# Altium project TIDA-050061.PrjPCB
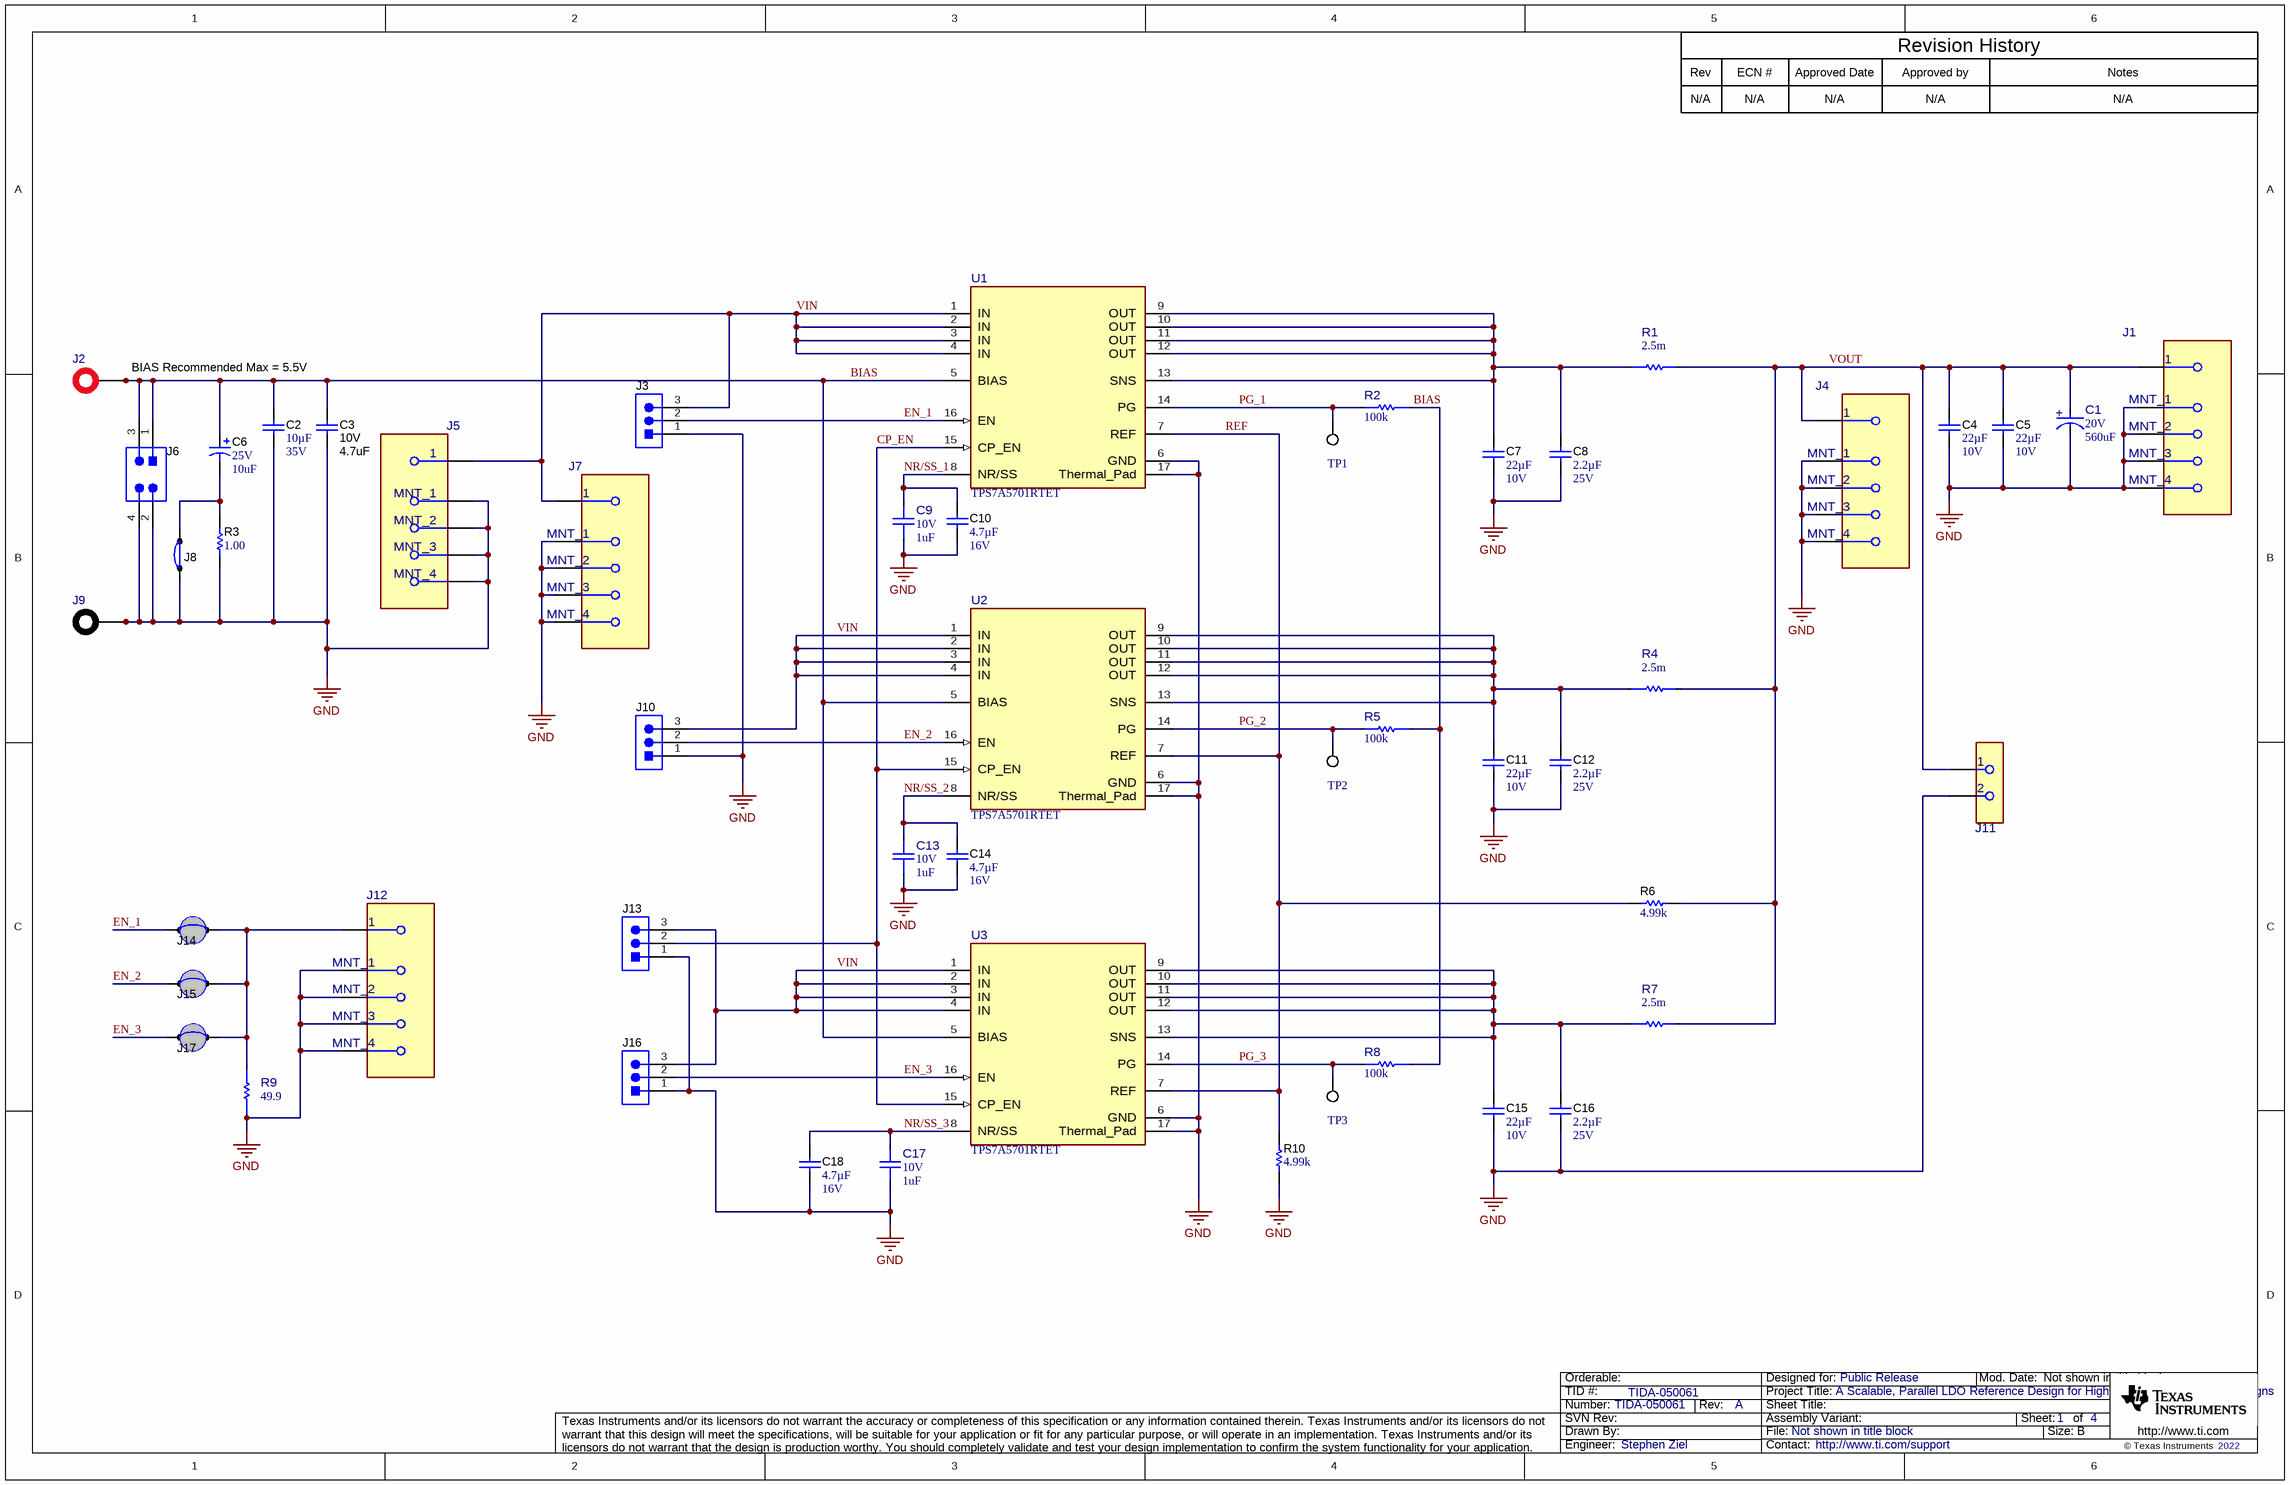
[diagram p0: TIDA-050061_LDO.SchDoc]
TID: TIDA-050061; TechSupport: http://www.ti.com/support; SCH_Rev: A; PRJ_Title: A Scalable, Parallel LDO Reference Design for High Speed and Low Noise Designs; PRJ_Number: TIDA-050061; PRJ_Engineer: Stephen Ziel; PRJ_Customer: Public Release; PCB_Rev: A; PCB_Layout: Stephen Ziel; CopyrightYear: 2022
4 sheets, 179 parts. Net scope: global (net labels, ports and power ports of the same name join across sheets).
Board file: TIDA-050061.PcbDoc
Sheets:
  TIDA-050061_LDO.SchDoc
  TIDA-050061_Load.SchDoc
  TIDA-050061_Input_Cap.SchDoc
  TIDA-050061_Hardware.SchDoc

## Sheet TIDA-050061_LDO.SchDoc
size 431 x 279 mm; Date: Not shown in title block; ApprovedBy: Not shown in title block; CheckedBy: Not shown in title block; Author: Not shown in title block; CompanyName: Not shown in title block; Engineer: Not shown in title block; Organization: Not shown in title block; Address1: Not shown in title block; Address2: Not shown in title block; Address3: Not shown in title block; Address4: Not shown in title block; DocumentNumber: 1; Revision: Use project parameter SCH_Rev; SheetNumber: 1; SheetTotal: 4; PageSetup: Record=PageOptions¦CenterHorizontal=True¦CenterVertical=True¦PrintScale=1.00¦XCorrection=1.00¦YCorrection=1.00¦PrintKind=0¦BorderSize=5000000¦LeftOffset=0¦BottomOffset=0¦Orientation=2¦PaperLength=1000¦PaperWidth=1000¦Scale=100¦PaperSource=15¦PrintQuality=600¦MediaType=1¦DitherType=10¦PaperKind=Letter¦PrintScaleMode=1

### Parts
C1  VDC_V: 20V  ValueDisplayed: 560uF  [FP-20SEF560M_RADIAL-MFG]  (hidden comment: 20SEF560M)
C2  Cap_F: 10µF  VDC_V: 35V  [1210_270]  (hidden comment: GRM32ER7YA106KA12K)
C3  VDC_V: 10V  ValueDisplayed: 4.7uF  [0603]  (hidden comment: C0603C475K8PACTU)
C4  Cap_F: 22µF  VDC_V: 10V  [0805_HV]  (hidden comment: GRM21BZ71A226ME15L)
C5  Cap_F: 22µF  VDC_V: 10V  [0805_HV]  (hidden comment: GRM21BZ71A226ME15L)
C6  VDC_V: 25V  ValueDisplayed: 10uF  [6032-28]  (hidden comment: TPSC106M025R0500)
C7  Cap_F: 22µF  VDC_V: 10V  [0805_HV]  (hidden comment: GRM21BZ71A226ME15L)
C8  Cap_F: 2.2µF  VDC_V: 25V  [0805_HV]  (hidden comment: TMK212B7225KG-TR)
C9  VDC_V: 10V  ValueDisplayed: 1uF  [FP-GMC04X7R105K10NT_0402-IPC_A]  (hidden comment: GMC04X7R105K10NT)
C10  Cap_F: 4.7µF  VDC_V: 16V  [0603]  (hidden comment: GRM188Z71C475KE21D)
C11  Cap_F: 22µF  VDC_V: 10V  [0805_HV]  (hidden comment: GRM21BZ71A226ME15L)
C12  Cap_F: 2.2µF  VDC_V: 25V  [0805_HV]  (hidden comment: TMK212B7225KG-TR)
C13  VDC_V: 10V  ValueDisplayed: 1uF  [FP-GMC04X7R105K10NT_0402-IPC_A]  (hidden comment: GMC04X7R105K10NT)
C14  Cap_F: 4.7µF  VDC_V: 16V  [0603]  (hidden comment: GRM188Z71C475KE21D)
C15  Cap_F: 22µF  VDC_V: 10V  [0805_HV]  (hidden comment: GRM21BZ71A226ME15L)
C16  Cap_F: 2.2µF  VDC_V: 25V  [0805_HV]  (hidden comment: TMK212B7225KG-TR)
C17  VDC_V: 10V  ValueDisplayed: 1uF  [FP-GMC04X7R105K10NT_0402-IPC_A]  (hidden comment: GMC04X7R105K10NT)
C18  Cap_F: 4.7µF  VDC_V: 16V  [0603]  (hidden comment: GRM188Z71C475KE21D)
J1  RF12-07H-T-00-50-G  [FP-RF12-07H-T-00-50-G_CONN_MMCX-MFG]  (value not drawn)
J2  571-0500  [571-0500]  (value not drawn)
J3  61300311121  [WURTH_61300311121]  (value not drawn)
J4  RF2-04A-T-00-50-G  [FP-RF2-04A-T-00-50-G_CONN_RF_7MM00_7MM00-MFG]  (value not drawn)
J5  RF12-07H-T-00-50-G  [FP-RF12-07H-T-00-50-G_CONN_MMCX-MFG]  (value not drawn)
J6  TSW-102-07-G-D  [TSW-102-07-G-D]  (value not drawn)
J7  RF2-04A-T-00-50-G  [FP-RF2-04A-T-00-50-G_CONN_RF_7MM00_7MM00-MFG]  (value not drawn)
J8  JMP-36-30X40SMT  [JMP-36-30X40SMT]  (value not drawn)
J9  571-0100  [571-0100]  (value not drawn)
J10  61300311121  [WURTH_61300311121]  (value not drawn)
J11  691137710002  [FP-691137710002_HDR2-MFG]  (value not drawn)
J12  RF2-04A-T-00-50-G  [FP-RF2-04A-T-00-50-G_CONN_RF_7MM00_7MM00-MFG]  (value not drawn)
J13  61300311121  [WURTH_61300311121]  (value not drawn)
J14  JMP-36-30X40SMT  [JMP-36-30X40SMT]  (value not drawn)
J15  JMP-36-30X40SMT  [JMP-36-30X40SMT]  (value not drawn)
J16  61300311121  [WURTH_61300311121]  (value not drawn)
J17  JMP-36-30X40SMT  [JMP-36-30X40SMT]  (value not drawn)
R1  value 2.5m  [FP-ULR1S-R0025FT2_1206-MFG]  (hidden comment: ULR1S-R0025FT2)
R2  value 100k  [FP-CRCW0402100KFKEDC_0402-IPC_A]  (hidden comment: CRCW0402100KFKEDC)
R3  ValueDisplayed: 1.00  [0805_HV]  (hidden comment: ERJ-6BQF1R0V)
R4  value 2.5m  [FP-ULR1S-R0025FT2_1206-MFG]  (hidden comment: ULR1S-R0025FT2)
R5  value 100k  [FP-CRCW0402100KFKEDC_0402-IPC_A]  (hidden comment: CRCW0402100KFKEDC)
R6  ValueDisplayed: 4.99k  [0402]  (hidden comment: CRCW04024K99FKED)
R7  value 2.5m  [FP-ULR1S-R0025FT2_1206-MFG]  (hidden comment: ULR1S-R0025FT2)
R8  value 100k  [FP-CRCW0402100KFKEDC_0402-IPC_A]  (hidden comment: CRCW0402100KFKEDC)
R9  value 49.9  [FP-CRCW120649R9FKEAHP_1206-MFG]  (hidden comment: CRCW120649R9FKEAHP)
R10  ValueDisplayed: 4.99k  [0402]  (hidden comment: CRCW04024K99FKED)
TP1  5016  [Testpoint_Keystone_Compact]  (value not drawn)
TP2  5016  [Testpoint_Keystone_Compact]  (value not drawn)
TP3  5016  [Testpoint_Keystone_Compact]  (value not drawn)
U1  TPS7A5701RTET  [RTE0016J-OV-MFG]
U2  TPS7A5701RTET  [RTE0016J-OV-MFG]
U3  TPS7A5701RTET  [RTE0016J-OV-MFG]

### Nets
GND: C1.1(CATHODE) C2.2 C3.2 C4.2 C5.2 C7.2 C8.2 C9.1 C10.2 C11.2 C12.2 C13.1 C14.2 C15.2 C16.2 C17.1 C18.2 J1.2(MNT_1) J1.3(MNT_2) J1.4(MNT_3) J1.5(MNT_4) J3.1 J4.2(MNT_1) J4.3(MNT_2) J4.4(MNT_3) J4.5(MNT_4) J5.2(MNT_1) J5.3(MNT_2) J5.4(MNT_3) J5.5(MNT_4) J6.2 J6.4 J7.2(MNT_1) J7.3(MNT_2) J7.4(MNT_3) J7.5(MNT_4) J8.1 J9.1 J9.2 J10.1 J11.2 J12.2(MNT_1) J12.3(MNT_2) J12.4(MNT_3) J12.5(MNT_4) J13.1 J16.1 R3.1 R9.1 R10.1 U1.6(GND) U1.17(Thermal_Pad) U2.6(GND) U2.17(Thermal_Pad) U3.6(GND) U3.17(Thermal_Pad)
BIAS: C2.1 C3.1 C6.1(+) J2.1 J2.2 J6.1 J6.3 R2.1 R5.1 R8.1 U1.5(BIAS) U2.5(BIAS) U3.5(BIAS)
CP_EN: J13.2 U1.15(CP_EN) U2.15(CP_EN) U3.15(CP_EN)
EN_1: J3.2 J14.1 U1.16(EN)
EN_2: J10.2 J15.1 U2.16(EN)
EN_3: J16.2 J17.1 U3.16(EN)
NR/SS_1: C9.2 C10.1 U1.8(NR/SS)
NR/SS_2: C13.2 C14.1 U2.8(NR/SS)
NR/SS_3: C17.2 C18.1 U3.8(NR/SS)
PG_1: R2.2 TP1.1 U1.14(PG)
PG_2: R5.2 TP2.1 U2.14(PG)
PG_3: R8.2 TP3.1 U3.14(PG)
REF: R6.2 R10.2 U1.7(REF) U2.7(REF) U3.7(REF)
VIN: J3.3 J5.1 J7.1 J10.3 J13.3 J16.3 U1.1(IN) U1.2(IN) U1.3(IN) U1.4(IN) U2.1(IN) U2.2(IN) U2.3(IN) U2.4(IN) U3.1(IN) U3.2(IN) U3.3(IN) U3.4(IN)
VOUT: C1.2(ANODE) C4.1 C5.1 J1.1 J4.1 J11.1 R1.2 R4.2 R6.1 R7.2
NetC6_2: C6.2(-) J8.2 R3.2
NetC7_1: C7.1 C8.1 R1.1 U1.9(OUT) U1.10(OUT) U1.11(OUT) U1.12(OUT) U1.13(SNS)
NetC11_1: C11.1 C12.1 R4.1 U2.9(OUT) U2.10(OUT) U2.11(OUT) U2.12(OUT) U2.13(SNS)
NetC15_1: C15.1 C16.1 R7.1 U3.9(OUT) U3.10(OUT) U3.11(OUT) U3.12(OUT) U3.13(SNS)
NetJ12_1: J12.1 J14.2 J15.2 J17.2 R9.2

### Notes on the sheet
- Rev
- N/A
- ECN #
- Approved Date
- Approved by
- Revision History
- Notes
- BIAS Recommended Max = 5.5V

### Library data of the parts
C1 = CMP-0093206-1: Cap Aluminum Polymer 560uF 20VDC 20% (10 X 13mm) Radial 5mm 0.012 Ohm 1700mA 1000h 125C; Manufacturer: Panasonic; Cap_F: 560µF; IRMS_A: 1.7A; AEC Qualified: No; Value: 560µF; Dissipation Factor: 12%; Life: 1000Hours; Leakage Current: 2240uA; Esr: 12m
C2 = CMP-0081639-1: CAP, CERM, 10 µF, 35 V,+/- 10%, X7R, 1210; Manufacturer: MuRata; Value: 10uF; SizeZ_mm: 2.7; AEC Qualified: N; TaMin_C: -55°C; ESR_ohm: 1m; SizeAreaWB_mm2: 14.7; Value1: 0.001 ohm; U/M: EA; TaMax_C: 125°C; SizeX_mm: 3.2; SizeY_mm: 2.5; Cap_Case: 1210; SizeArea_mm2: 8; IRMS_A: 6A; AEC Category: Q200
C3 = CMP-0006949-4: CAP, CERM, 4.7 uF, 10 V, +/- 10%, X5R, 0603; Manufacturer: Kemet; TaMin_C: -55°C; ESR_ohm: 6m; Polarized: N; SizeAreaWB_mm2: 4.68; Value1: 0.006 ohm; U/M: EA; Value: 4.7uF; TaMax_C: 85°C; SizeZ_mm: 1; SizeX_mm: 1.6; SizeY_mm: 0.8; SizeArea_mm2: 1.28; Cap_F: 4.7µF; IRMS_A: 7.24A; AEC Category: Q200
C4 C5 C7 C11 C15 = CMP-0008377-2: CAP, CERM, 22 uF, 10 V, +/- 20%, X7R, 0805; Manufacturer: MuRata; SizeY_mm: 1.25; Cap_Case: 0805; SizeArea_mm2: 2.5; AEC Qualified: N; AEC Category: Q200; ValueDisplayed: 22uF; TaMin_C: -55°C; SizeAreaWB_mm2: 6.75; Value1: Unknown; U/M: EA; Value: 22uF; TaMax_C: 125°C; SizeZ_mm: 1.45; SizeX_mm: 2
C6 = CMP-0011645-1: CAP, TA, 10 uF, 25 V, +/- 20%, 0.5 ohm, SMD; Manufacturer: AVX; TaMin_C: -55°C; ESR_ohm: 0.5; Polarized: Y; SizeAreaWB_mm2: 41.6; Value1: 0.5 ohm; U/M: EA; Value: 10uF; TaMax_C: 125°C; SizeZ_mm: 2.8; SizeX_mm: 6; SizeY_mm: 3.2; Cap_Case: C; SizeArea_mm2: 19.2; CompType: Capacitor; Cap_F: 10µF; IRMS_A: 422mA; AEC Category: Q200
C8 C12 C16 = CMP-0080705-2: CAP, CERM, 2.2 µF, 25 V,+/- 10%, X7R, 0805; Manufacturer: Taiyo Yuden; SizeY_mm: 1.25; Cap_Case: 0805; SizeArea_mm2: 2.5; AEC Qualified: N; AEC Category: Q200; TaMin_C: -55°C; SizeAreaWB_mm2: 6.75; U/M: EA; Value: 2.2uF; TaMax_C: 125°C; SizeZ_mm: 1.45; SizeX_mm: 2
C9 C13 C17 = CMP-0093200-1: 1µF ±10% 10V Ceramic Capacitor X7R 0402 (1005 Metric); Manufacturer: Cal-Chip Electronics; TempCo: 15%; SizeZ_mm: 0.6mm; AEC Qualified: No
C10 C14 C18 = CMP-0064936-1: CAP, CERM, 4.7 uF, 16 V,+/- 10%, X7R, 0603; Manufacturer: MuRata; TaMin_C: -55°C; Polarized: N; SizeAreaWB_mm2: 4.68; Value1: Unknown; U/M: EA; Value: 4.7uF; TaMax_C: 125°C; SizeZ_mm: 1; SizeX_mm: 1.6; SizeY_mm: 0.8; SizeArea_mm2: 1.28; AEC Category: Q200
J1 J5 = CMP-0096285-1: MMCX Connector Jack, Female Socket 50Ohm Through Hole Solder; Manufacturer: Adam Tech; ContactFinish: Gold; Is Female: yes; Dielectric Material: TEFLON; SizeZ_mm: 0.207inch; Impedance: 50Ω; AEC Qualified: No; Conn Orientation: Vertical
J2 = CMP-0055393-3: Standard Banana Jack, insulated, 10A, red; Manufacturer: DEM Manufacturing; Green_REACh: Incomplete; Green_Lifecycle: Not Set
J3 J10 J13 J16 = CMP-0054796-2: Header, 2.54 mm, 3x1, Gold, TH; Manufacturer: Wurth Elektronik; Green_REACh: Passed; Green_Lifecycle: Active; Cert_UL: Y; Gender: Male; Pitch_mm: 2.54; Row_Count: 1; Shrouded: N
J4 J7 = CMP-0096117-1: SMA Connector Jack, Female Socket 50Ohm Through Hole Solder; Manufacturer: Adam Tech; ContactFinish: Gold; Voltage_V: 500V; AEC Qualified: No; Impedance: 50Ω; Dielectric Material: PTFE; Is Female: yes; SizeZ_mm: 0.407inch; Frequency_Fixed: 6GHz; Conn Orientation: Vertical
J6 = CMP-0075404-1: Header, 100mil, 2x2, Gold, TH; Manufacturer: Samtec; Pitch_mm: 2.54; Cert_VDE: N; Gender: Male; Cert_CSA: Y; Voltage_V: 550V; Green_REACh: Passed; Current_A: 6.3A; CT: False; Green_Lifecycle: Active; Row_Count: 2; CNHeader: True
J8 J14 J15 J17 = CMP-0003883-1: Jumper, SMT; Manufacturer: Any
J9 = CMP-0055389-3: Standard Banana Jack, insulated, 10A, black; Manufacturer: DEM Manufacturing; Green_REACh: Incomplete; Green_Lifecycle: Not Set
J11 = CMP-0087503-1: TERM BLK 2POS SIDE ENTRY 5MM PCB; Manufacturer: Würth Elektronik; ContactFinish: Tin,Nickel; Current_A: 16A; Row_Count: 1; Voltage_V: 300V; Symbol Name: SYM-691137710002
J12 = CMP-0096117-1: SMA Connector Jack, Female Socket 50Ohm Through Hole Solder; Manufacturer: Adam Tech; AEC Qualified: No; Impedance: 50Ω; Dielectric Material: PTFE; Is Female: yes; SizeZ_mm: 0.407inch; Frequency_Fixed: 6GHz; Conn Orientation: Vertical; Voltage_V: 500V; ContactFinish: Gold
R1 R4 R7 = CMP-0095593-1: Fixed Resistor, Metal Alloy, 1W, 0.0025ohm, 1% +/-Tol, 50ppm/Cel, Surface Mount, 1206; Manufacturer: Welwyn; TempCo: 50ppm/°C; SizeZ_mm: 0.8mm; AEC Qualified: Yes; AEC Grade: Grade 0
R2 R5 R8 = CMP-0092204-1: 100 kOhms ±1% 0.063W, 1/16W Chip Resistor 0402 (1005 Metric)  Thick Film; Manufacturer: Vishay; Power_W: 63mW; AEC Qualified: No; TempCo: 100ppm/°C; SizeZ_mm: 0.35mm; VDC_V: 50V
R3 = CMP-0074786-1: RES, 1.00, 1%, 0.333 W, AEC-Q200 Grade 1, 0805; Manufacturer: Panasonic; Power_W: 333mW; TempCo: 200 ppm/C; Value_Code: 1R00; U/M: EA; Value: 1.00; EIA_Code: E96; Res_ohm: 1; SizeX_mm: 2.0; SizeY_mm: 1.25; SizeZ_mm: 1.45; Value2: 0.333W; SizeArea_mm2: 2.5; AEC Qualified: Y; AEC Category: Q200
R6 R10 = CMP-0026414-2: RES, 4.99 k, 1%, 0.063 W, AEC-Q200 Grade 0, 0402; Manufacturer: Vishay-Dale; Power_W: 63mW; TempCo: 100 ppm/C; Value_Code: 4k99; Value: 4.99k; EIA_Code: E96; SizeX_mm: 1; SizeY_mm: 0.5; SizeZ_mm: 0.6; Value2: 0.063W; AEC Qualified: Y; VDC_V: 50V; AEC Category: Q200; AEC Grade: 0
R9 = CMP-0093196-1: RES Thick Film, 49.9Ω, 1%, 0.75W, 100ppm/°C, 1206; Manufacturer: Vishay Dale; Power_W: 750mW; SizeZ_mm: 0.65mm; AEC Qualified: Yes; AEC Grade: Grade 0; VDC_V: 200V
TP1-TP3 = CMP-0055153-1: Test Point, Compact, SMT; Manufacturer: Keystone; CNHeader: FALSE; Green_Lifecycle: Active; Green_REACh: Passed; CT: TRUE
U1-U3 = CMP-0090637-2: 5-A, Low-VIN (0.7V), Low-Noise, High-Accuracy, Ultra-Low Dropout (LDO) Voltage Regulator; Manufacturer: Texas Instruments; Max Supply Voltage: 6V; Min Supply Voltage: 700mV; Standoff Height: 0mm; Dropout Voltage: 100mV; Number Of Outputs: 1; AEC Category: Q200; Nominal Supply Current: 10mA; Output Type: AdjustableProgrammable; Accuracy Percentage: 1%; AEC Qualified: Yes; Output Voltage: 0.5-5.2V; CompType: IC; TJmax_C: +125°C; SizeZ_mm: 0.8mm

## Sheet TIDA-050061_Load.SchDoc
size 431 x 279 mm; Date: Not shown in title block; ApprovedBy: Not shown in title block; CheckedBy: Not shown in title block; Author: Not shown in title block; CompanyName: Not shown in title block; Engineer: Not shown in title block; Organization: Not shown in title block; Address1: Not shown in title block; Address2: Not shown in title block; Address3: Not shown in title block; Address4: Not shown in title block; DocumentNumber: 2; Revision: Use project parameter SCH_Rev; SheetNumber: 2; SheetTotal: 4; PageSetup: Record=PageOptions¦CenterHorizontal=True¦CenterVertical=True¦PrintScale=1.00¦XCorrection=1.00¦YCorrection=1.00¦PrintKind=0¦BorderSize=5000000¦LeftOffset=0¦BottomOffset=0¦Orientation=2¦PaperLength=1000¦PaperWidth=1000¦Scale=100¦PaperSource=15¦PrintQuality=600¦MediaType=1¦DitherType=10¦PaperKind=Letter¦PrintScaleMode=1
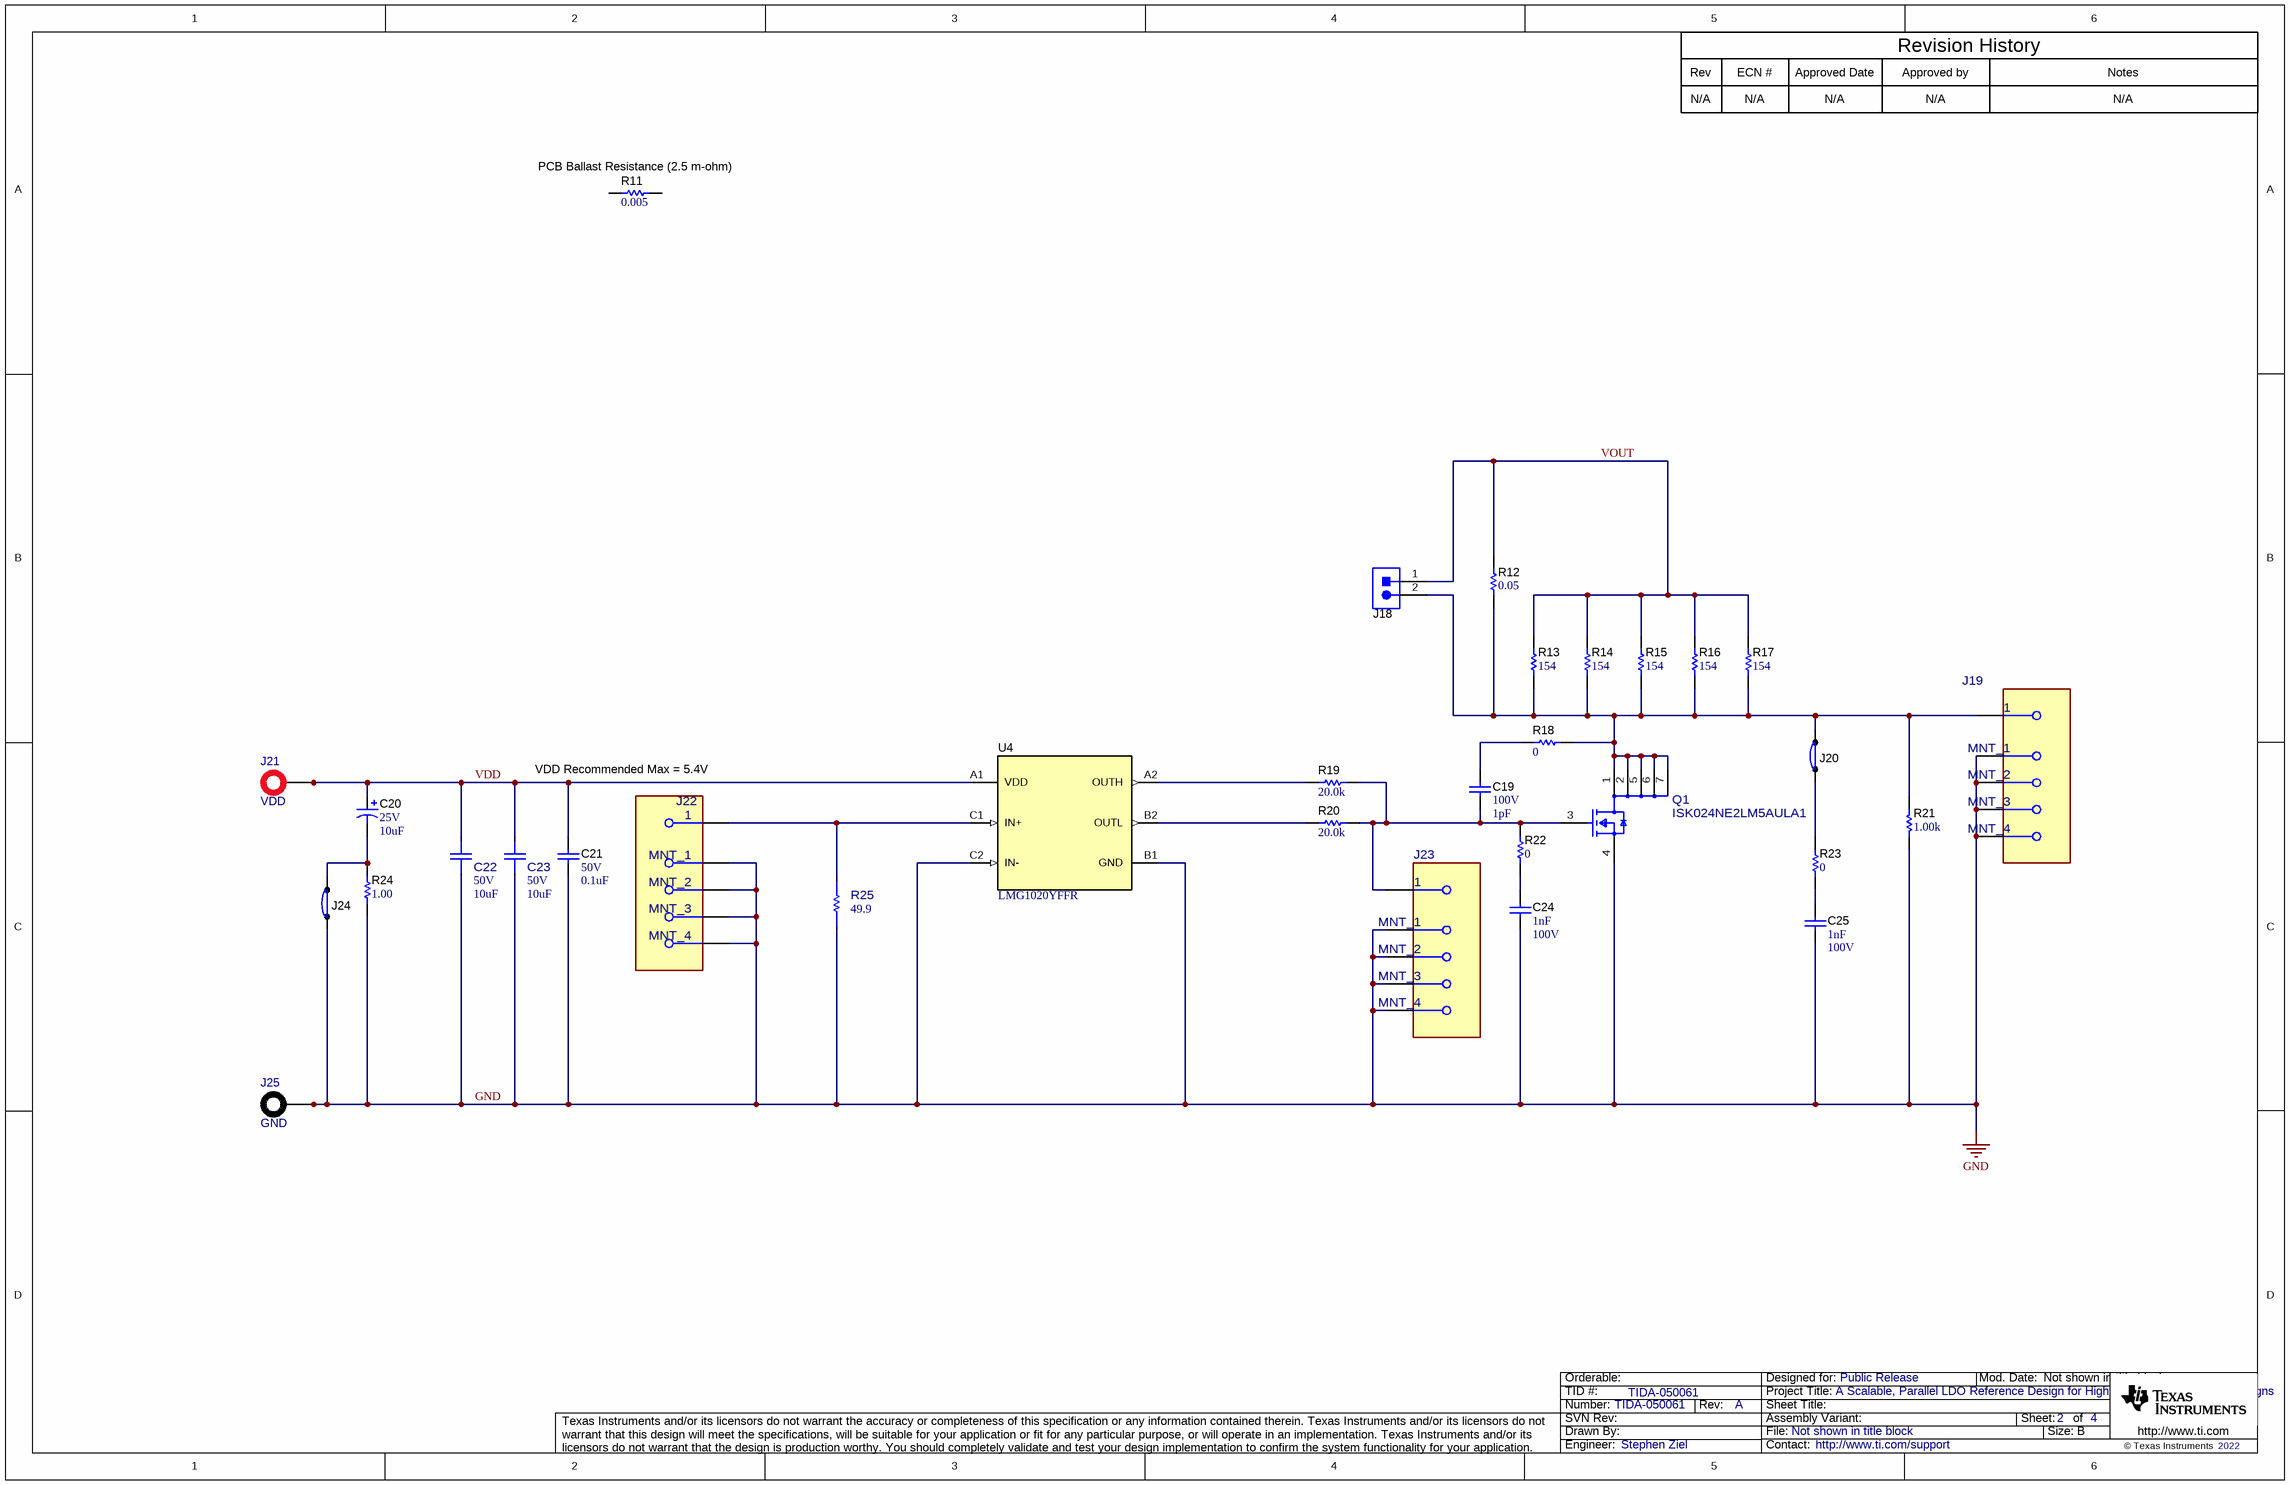
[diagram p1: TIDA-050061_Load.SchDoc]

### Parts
C19  VDC_V: 100V  ValueDisplayed: 1pF  [0805]  (hidden comment: CL05A105KP5NNNC-R)
C20  VDC_V: 25V  ValueDisplayed: 10uF  [6032-28]  (hidden comment: TPSC106M025R0500)
C21  VDC_V: 50V  ValueDisplayed: 0.1uF  [0402]  (hidden comment: C1005X7R1H104K050BB)
C22  VDC_V: 50V  ValueDisplayed: 10uF  [FP-GMC31X7R106K50NT_1206-MFG]  (hidden comment: GMC31X7R106K50NT)
C23  VDC_V: 50V  ValueDisplayed: 10uF  [FP-GMC31X7R106K50NT_1206-MFG]  (hidden comment: GMC31X7R106K50NT)
C24  Cap_F: 1nF  VDC_V: 100V  [0603]  (hidden comment: 06031C102JAT2A)
C25  Cap_F: 1nF  VDC_V: 100V  [0603]  (hidden comment: 06031C102JAT2A)
J18  PBC02SAAN  [Sullins_PBC02SAAN]  (value not drawn)
J19  RF12-07H-T-00-50-G  [FP-RF12-07H-T-00-50-G_CONN_MMCX-MFG]  (value not drawn)
J20  JMP-36-30X40SMT  [JMP-36-30X40SMT]  (value not drawn)
J21  VDD  [571-0500]
J22  RF2-04A-T-00-50-G  [FP-RF2-04A-T-00-50-G_CONN_RF_7MM00_7MM00-MFG]  (value not drawn)
J23  RF12-07H-T-00-50-G  [FP-RF12-07H-T-00-50-G_CONN_MMCX-MFG]  (value not drawn)
J24  JMP-36-30X40SMT  [JMP-36-30X40SMT]  (value not drawn)
J25  GND  [571-0100]
Q1  ISK024NE2LM5AULA1  [FP-ISK024NE2LM5AULA1_VSON6-MFG]
R11  ValueDisplayed: 0.005  [1206]  (hidden comment: WSL12065L000FEA18)
R12  ValueDisplayed: 0.05  [0612]  (hidden comment: ERJ-B2CFR05V)
R13  ValueDisplayed: 154  [1210]  (hidden comment: RC1210FR-07154RL)
R14  ValueDisplayed: 154  [1210]  (hidden comment: RC1210FR-07154RL)
R15  ValueDisplayed: 154  [1210]  (hidden comment: RC1210FR-07154RL)
R16  ValueDisplayed: 154  [1210]  (hidden comment: RC1210FR-07154RL)
R17  ValueDisplayed: 154  [1210]  (hidden comment: RC1210FR-07154RL)
R18  ValueDisplayed: 0  [0805_HV]  (hidden comment: ERJ-6GEY0R00V)
R19  ValueDisplayed: 20.0k  [0603]  (hidden comment: RC0603FR-0720KL)
R20  ValueDisplayed: 20.0k  [0603]  (hidden comment: RC0603FR-0720KL)
R21  ValueDisplayed: 1.00k  [0805_HV]  (hidden comment: ERJ-6ENF1001V)
R22  ValueDisplayed: 0  [0603]  (hidden comment: RMCF0603ZT0R00)
R23  ValueDisplayed: 0  [0603]  (hidden comment: RMCF0603ZT0R00)
R24  ValueDisplayed: 1.00  [0805_HV]  (hidden comment: ERJ-6BQF1R0V)
R25  value 49.9  [FP-CRCW120649R9FKEAHP_1206-MFG]  (hidden comment: CRCW120649R9FKEAHP)
U4  LMG1020YFFR  [YFF0006AEAE]

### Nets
GND: C21.2 C22.1 C23.1 C24.2 C25.2 J19.2(MNT_1) J19.3(MNT_2) J19.4(MNT_3) J19.5(MNT_4) J22.2(MNT_1) J22.3(MNT_2) J22.4(MNT_3) J22.5(MNT_4) J23.2(MNT_1) J23.3(MNT_2) J23.4(MNT_3) J23.5(MNT_4) J24.1 J25.1 J25.2 Q1.4(SOURCE) R21.1 R24.1 R25.1 U4.B1(GND) U4.C2(IN-)
VDD: C20.1(+) C21.1 C22.2 C23.2 J21.1 J21.2 U4.A1(VDD)
VOUT: J18.1 R12.2 R13.2 R14.2 R15.2 R16.2 R17.2
NetC19_1: C19.1 R18.1
NetC19_2: C19.2 J23.1 Q1.3(GATE) R19.2 R20.2 R22.2
NetC20_2: C20.2(-) J24.2 R24.2
NetC24_1: C24.1 R22.1
NetC25_1: C25.1 R23.1
NetJ18_2: J18.2 J19.1 J20.2 Q1.1(DRAIN) Q1.2(DRAIN) Q1.5(DRAIN) Q1.6(DRAIN) Q1.7(DRAIN) R12.1 R13.1 R14.1 R15.1 R16.1 R17.1 R18.2 R21.2
NetJ20_1: J20.1 R23.2
NetJ22_1: J22.1 R25.2 U4.C1(IN+)
NetR19_1: R19.1 U4.A2(OUTH)
NetR20_1: R20.1 U4.B2(OUTL)

Not connected (* = marked no-connect by the designer): R11 1 2

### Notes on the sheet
- Rev
- N/A
- ECN #
- Approved Date
- Approved by
- Revision History
- Notes
- (near R11) PCB Ballast Resistance (2.5 m-ohm)
- VDD Recommended Max = 5.4V

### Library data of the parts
C19 = CMP-0008040-1: CAP, CERM, 1 pF, 100 V, +/- 5%, C0G/NP0, 0805; Manufacturer: MuRata; PartNumber: GQM2195C2A1R0CB01D; TaMin_C: -55°C; Polarized: N; SizeAreaWB_mm2: 6.75; Value1: Unknown; U/M: EA; Value: 1pF; TaMax_C: 125°C; SizeZ_mm: 1.45; SizeX_mm: 2; SizeY_mm: 1.25; SizeArea_mm2: 2.5; AEC Category: Q200
C20 = CMP-0011645-1: as C6 on sheet TIDA-050061_LDO
C21 = CMP-0006297-2: CAP, CERM, 0.1 uF, 50 V, +/- 10%, X7R, 0402; Manufacturer: TDK; TaMin_C: -55°C; ESR_ohm: 39.064m; Polarized: N; SizeAreaWB_mm2: 3; Value1: 0.039064 ohm; U/M: EA; Value: 0.1uF; TaMax_C: 125°C; SizeZ_mm: 0.6; SizeX_mm: 1; SizeY_mm: 0.5; Cap_F: 100nF; IRMS_A: 814.669mA; AEC Category: Q200
C22 C23 = CMP-0093201-1: 10 µF ±10% 50V Ceramic Capacitor X7R 1206 (3216 Metric); Manufacturer: Cal-Chip Electronics; TempCo: 15%; Value: 10µF; SizeZ_mm: 1.8mm; AEC Qualified: No
C24 C25 = CMP-0006723-4: CAP, CERM, 1000 pF, 100 V, +/- 5%, X7R, 0603; Manufacturer: AVX; Value: 1000pF; SizeZ_mm: 1; AEC Qualified: N; TaMin_C: -55°C; ESR_ohm: 0.276; SizeAreaWB_mm2: 4.68; Value1: 0.276 ohm; U/M: EA; TaMax_C: 125°C; SizeX_mm: 1.6; SizeY_mm: 0.8; SizeArea_mm2: 1.28; AEC Category: Q200
J18 = CMP-0054566-1: Header, 100mil, 2x1, Gold, TH; Manufacturer: Sullins Connector Solutions; CNHeader: TRUE; Current_A: 3A; Green_Lifecycle: Active; Shrouded: N; Gender: Male; Green_REACh: Passed; Voltage_V: 1.8kV; Row_Count: 1; Pitch_mm: 2.54; CT: FALSE; Cert_UL: Y
J19 J23 = CMP-0096285-1: as J1 on sheet TIDA-050061_LDO
J20 J24 = CMP-0003883-1: Jumper, SMT; Manufacturer: Any
J21 = CMP-0055393-3: as J2 on sheet TIDA-050061_LDO
J22 = CMP-0096117-1: as J4 on sheet TIDA-050061_LDO
J25 = CMP-0055389-3: as J9 on sheet TIDA-050061_LDO
Q1 = CMP-0095537-1: 40 V optiMOS Power Transistor, Surface Mount 6-PQFN Dual (2x2); Manufacturer: Infineon; QgTyp_nC: 14.8nC @ 10V; Vgs_V: 16V; Threshold Vgs Min: 1.2V; Reverse Recovery Charge: 15.2nC; AEC Qualified: No; Pulse Drain Current: 221A; IdsMax_A: 20A; Rdson45_ohm: 1.9m; Number Of N Channels: 1; VdsMax_V: 1V; Transconductance: 100S; Turn On Delay Time: 7.2ns; Input Capacitace At Vds: 960pF @ 12V; ChMode: False; Power_W: 2.1W; Reverse Recovery Time: 23.6ns; Typ Forward Diode Voltage: 0.81V; SizeZ_mm: 0.9mm; Turn Off Delay Time: 14.6ns; TJmax_C: +150°C; Drain To Source Breakdown Voltage: 25V; Threshold Vgs Max: 2V
R11 = CMP-0084633-1: RES, 0.005, 1%, 0.5 W, AEC-Q200 Grade 0, 1206; Manufacturer: Vishay-Dale; Value_Code: 5L000; SizeArea_mm2: 5.12; Value: 0.005; SizeY_mm: 1.6; TempCo: 110 ppm/C; Value2: 0.5W; SizeZ_mm: 1.35; Res_ohm: 5m; Green_REACh: Incomplete; Power_W: 500mW; SizeX_mm: 3.2; AEC Qualified: Y; SizeAreaWB_mm2: 10.92; Green_Lifecycle: Active; EIA_Code: E96; AEC Grade: 0; AEC Category: Q200
R12 = CMP-0015056-3: RES, 0.05, 1%, 1 W, AEC-Q200 Grade 0, 0612; Manufacturer: Panasonic; Value_Code: R050; SizeZ_mm: 0.85; TempCo: 150 ppm/C; SizeAreaWB_mm2: 10.92; AEC Grade: 0; SizeY_mm: 3.2; AEC Qualified: Y; U/M: EA; AEC Category: Q200; EIA_Code: E96; SizeX_mm: 1.6; Value2: 1W; Value: 0.05; Res_ohm: 50m; SizeArea_mm2: 5.12
R13-R17 = CMP-0082786-1: RES, 154, 1%, 0.5 W, 1210; Manufacturer: Yageo; Power_W: 500mW; TempCo: 100 ppm/C; SizeAreaWB_mm2: 14.7; Value_Code: 154R; Value: 154; EIA_Code: E96; SizeX_mm: 3.2; SizeY_mm: 2.5; SizeZ_mm: 1.35; Value2: 0.5W; SizeArea_mm2: 8; AEC Qualified: N; VDC_V: 200V; AEC Category: Q200
R18 = CMP-0020616-3: RES, 0, 5%, 0.125 W, AEC-Q200 Grade 0, 0805; Manufacturer: Panasonic; Power_W: 125mW; TempCo: 600 ppm/C; Value_Code: 0000; Value: 0; EIA_Code: E24; SizeX_mm: 2; SizeY_mm: 1.25; SizeZ_mm: 1.45; Value2: 0.125W; SizeArea_mm2: 2.5; AEC Qualified: Y; VDC_V: 150V; AEC Category: Q200; SizeAreaWB_mm2: 6.75
R19 R20 = CMP-0022906-5: RES, 20.0 k, 1%, 0.1 W, 0603; Manufacturer: Yageo; Power_W: 100mW; TempCo: 100 ppm/C; Value_Code: 20k0; Value: 20.0k; EIA_Code: E96; Res_ohm: 20k; SizeX_mm: 1.6; SizeY_mm: 0.8; SizeZ_mm: 1; Value2: 0.1W; SizeArea_mm2: 1.28; AEC Qualified: N; VDC_V: 75V; AEC Category: Q200; SizeAreaWB_mm2: 4.68
R21 = CMP-0021519-3: RES, 1.00 k, 1%, 0.125 W, AEC-Q200 Grade 0, 0805; Manufacturer: Panasonic; Power_W: 125mW; TempCo: 100 ppm/C; Value_Code: 1k00; Value: 1.00k; EIA_Code: E96; Res_ohm: 1k; SizeX_mm: 2; SizeY_mm: 1.25; SizeZ_mm: 1.45; Value2: 0.125W; SizeArea_mm2: 2.5; AEC Qualified: Y; AEC Category: Q200; AEC Grade: 0; SizeAreaWB_mm2: 6.75
R22 R23 = CMP-0023343-3: RES, 0, 1%, 0.1 W, AEC-Q200 Grade 0, 0603; Manufacturer: Stackpole Electronics Inc; Power_W: 100mW; TempCo: ppm/C; U/M: EA; Value: 0; SizeX_mm: 1.6; SizeY_mm: 0.8; SizeZ_mm: 1; Value2: 0.1W; SizeArea_mm2: 1.28; AEC Qualified: Y; AEC Category: Q200
R24 = CMP-0074786-1: as R3 on sheet TIDA-050061_LDO
R25 = CMP-0093196-1: as R9 on sheet TIDA-050061_LDO
U4 = CMP-0084842-1: 5V, 7A/5A Low Side GaN Driver With 60MHz/1ns Speed, YFF0006AEAE (DSBGA-6); Manufacturer: Texas Instruments; Alternate PartNumber: LMG1020YFFT; SizeArea_mm2: 1.076848; Rating: Catalog; SizeZ_mm: 0.625; AEC Category: Q200; CompType: IC; SizeY_mm: 1.258; SizeAreaWB_mm2: 4.190848; AEC Qualified: N; SizeX_mm: 0.856

## Sheet TIDA-050061_Input_Cap.SchDoc
size 431 x 279 mm; Date: Not shown in title block; ApprovedBy: Not shown in title block; CheckedBy: Not shown in title block; Author: Not shown in title block; CompanyName: Not shown in title block; Engineer: Not shown in title block; Organization: Not shown in title block; Address1: Not shown in title block; Address2: Not shown in title block; Address3: Not shown in title block; Address4: Not shown in title block; DocumentNumber: 3; Revision: Use project parameter SCH_Rev; SheetNumber: 3; SheetTotal: 4; PageSetup: Record=PageOptions¦CenterHorizontal=True¦CenterVertical=True¦PrintScale=1.00¦XCorrection=1.00¦YCorrection=1.00¦PrintKind=0¦BorderSize=5000000¦LeftOffset=0¦BottomOffset=0¦Orientation=2¦PaperLength=1000¦PaperWidth=1000¦Scale=100¦PaperSource=15¦PrintQuality=600¦MediaType=1¦DitherType=10¦PaperKind=Letter¦PrintScaleMode=1
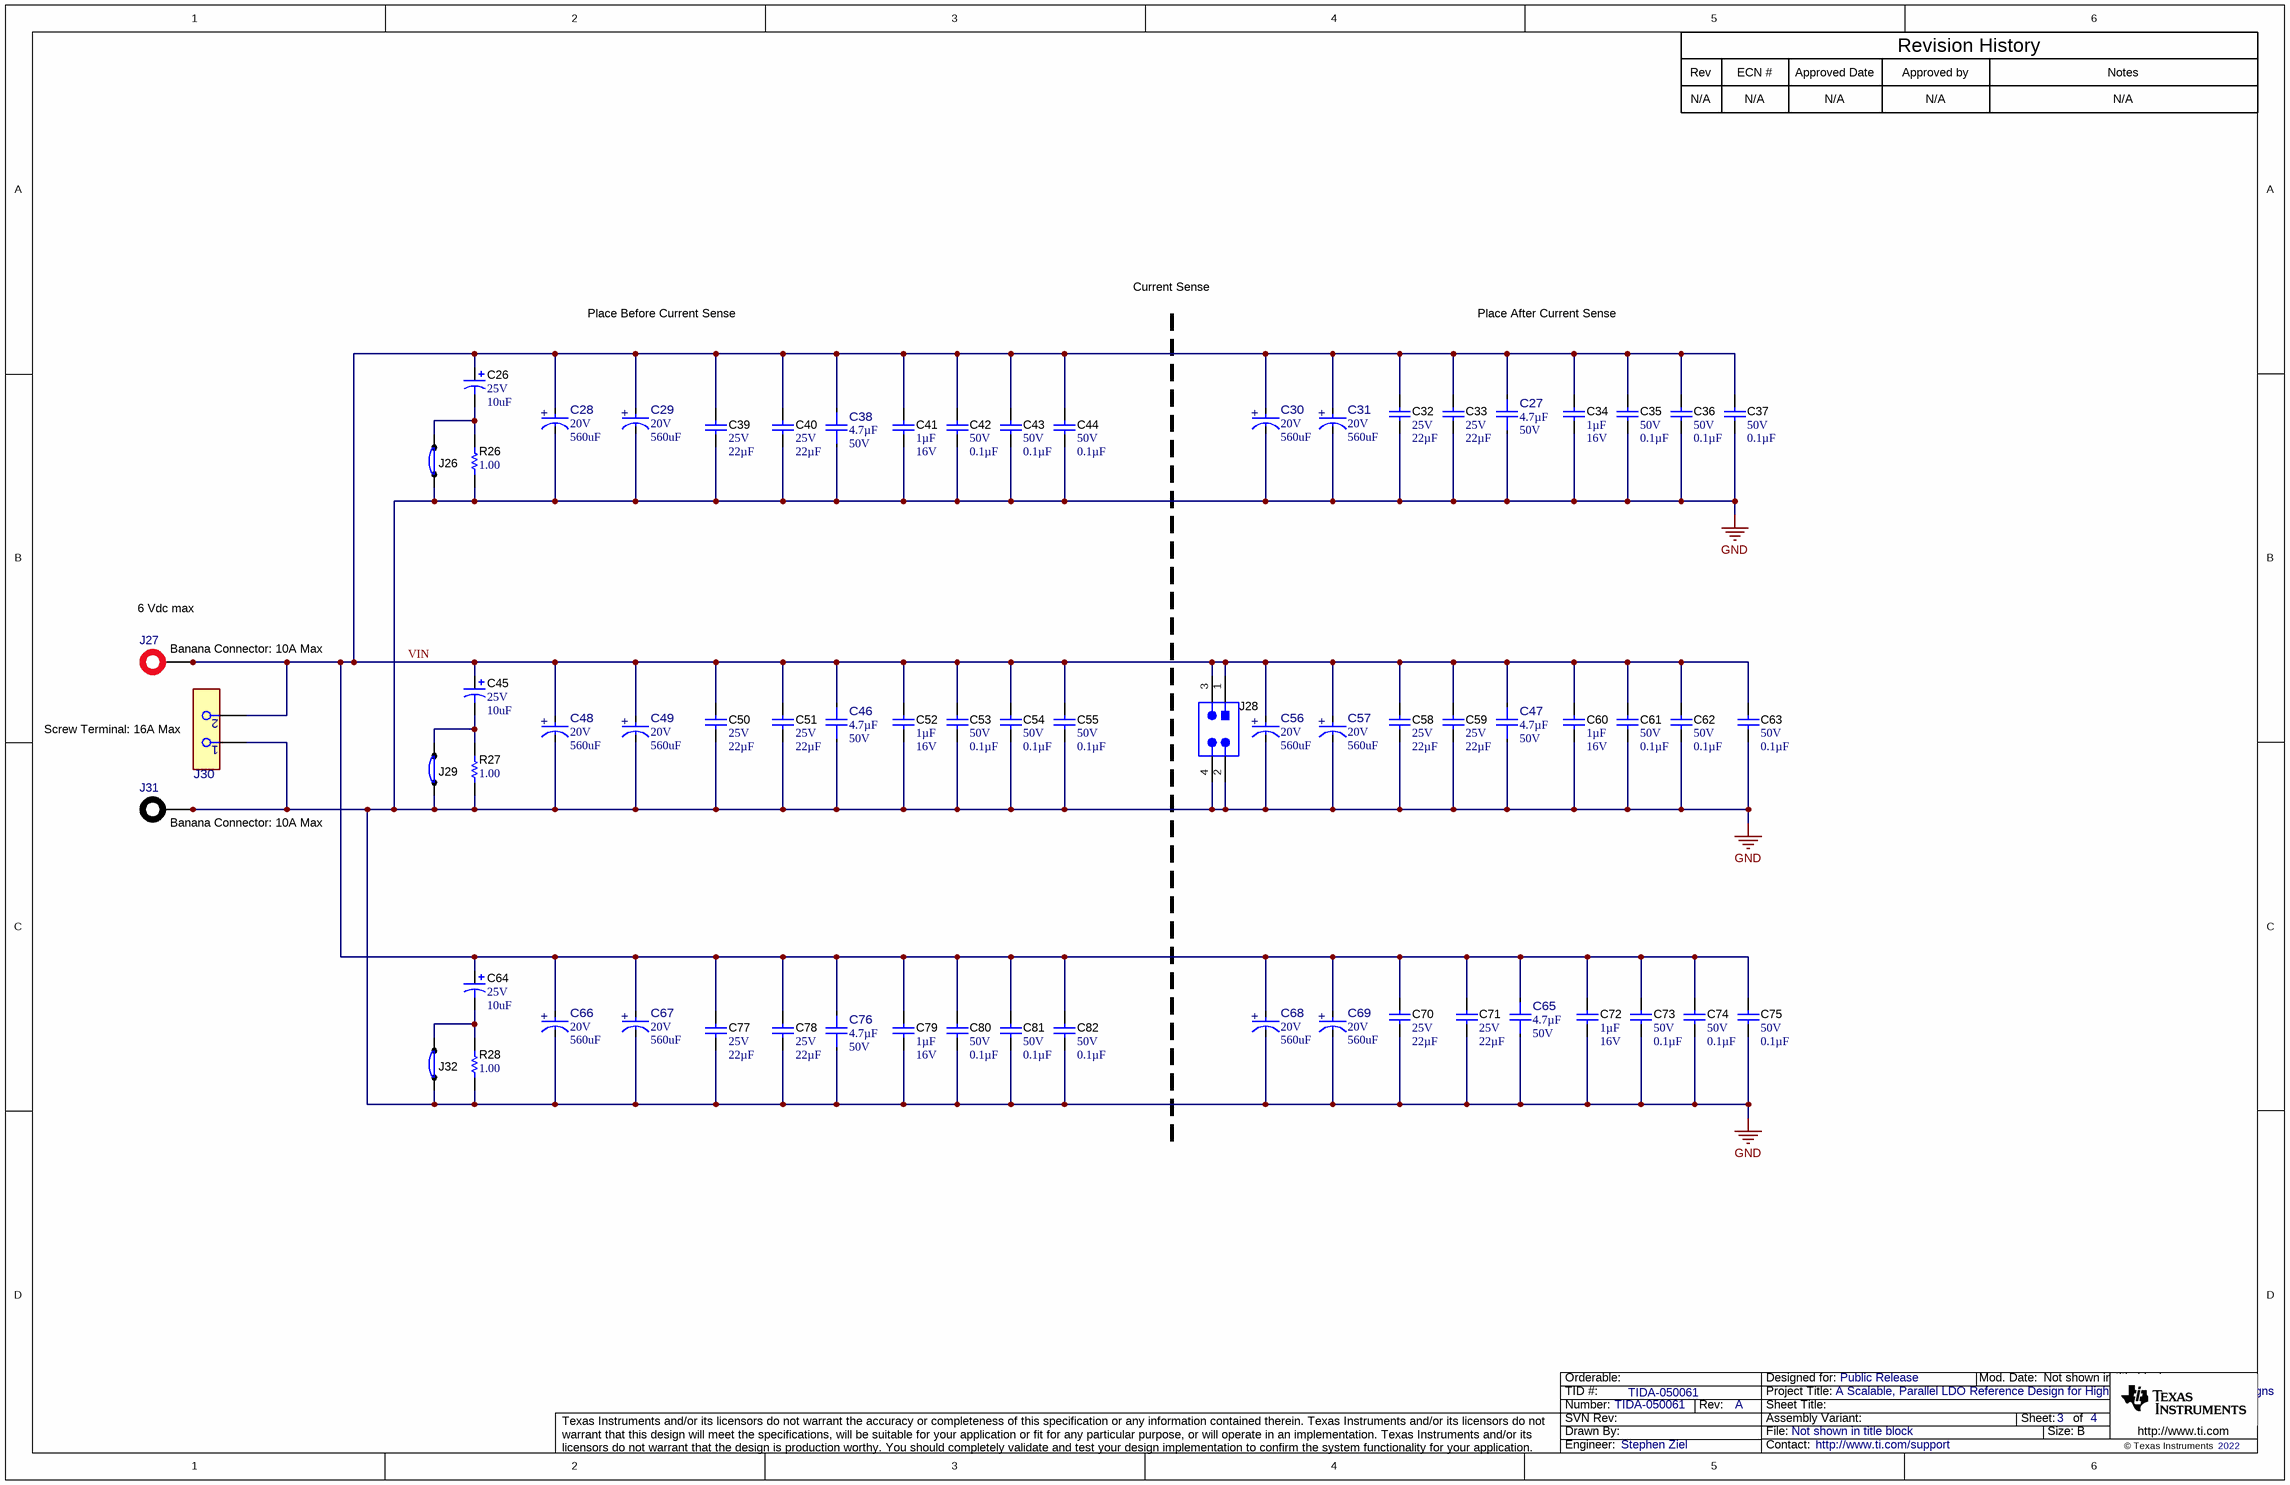
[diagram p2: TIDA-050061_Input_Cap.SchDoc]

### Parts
C26  VDC_V: 25V  ValueDisplayed: 10uF  [6032-28]  (hidden comment: TPSC106M025R0500)
C27  Cap_F: 4.7µF  VDC_V: 50V  [FP-CGA4J1X7R1H475K125AC_0805-IPC_A]  (hidden comment: CGA4J1X7R1H475K125AC)
C28  VDC_V: 20V  ValueDisplayed: 560uF  [FP-20SEF560M_RADIAL-MFG]  (hidden comment: 20SEF560M)
C29  VDC_V: 20V  ValueDisplayed: 560uF  [FP-20SEF560M_RADIAL-MFG]  (hidden comment: 20SEF560M)
C30  VDC_V: 20V  ValueDisplayed: 560uF  [FP-20SEF560M_RADIAL-MFG]  (hidden comment: 20SEF560M)
C31  VDC_V: 20V  ValueDisplayed: 560uF  [FP-20SEF560M_RADIAL-MFG]  (hidden comment: 20SEF560M)
C32  VDC_V: 25V  ValueDisplayed: 22µF  [1210_270M]  (hidden comment: CL32B226KAJNFNE)
C33  VDC_V: 25V  ValueDisplayed: 22µF  [1210_270M]  (hidden comment: CL32B226KAJNFNE)
C34  Cap_F: 1µF  VDC_V: 16V  [0805_HV]  (hidden comment: C0805C105K4RACAUTO)
C35  VDC_V: 50V  ValueDisplayed: 0.1µF  [0402M]  (hidden comment: UMK105B7104MV-FR)
C36  VDC_V: 50V  ValueDisplayed: 0.1µF  [0402M]  (hidden comment: UMK105B7104MV-FR)
C37  VDC_V: 50V  ValueDisplayed: 0.1µF  [0402M]  (hidden comment: UMK105B7104MV-FR)
C38  Cap_F: 4.7µF  VDC_V: 50V  [FP-CGA4J1X7R1H475K125AC_0805-IPC_A]  (hidden comment: CGA4J1X7R1H475K125AC)
C39  VDC_V: 25V  ValueDisplayed: 22µF  [1210_270M]  (hidden comment: CL32B226KAJNFNE)
C40  VDC_V: 25V  ValueDisplayed: 22µF  [1210_270M]  (hidden comment: CL32B226KAJNFNE)
C41  Cap_F: 1µF  VDC_V: 16V  [0805_HV]  (hidden comment: C0805C105K4RACAUTO)
C42  VDC_V: 50V  ValueDisplayed: 0.1µF  [0402M]  (hidden comment: UMK105B7104MV-FR)
C43  VDC_V: 50V  ValueDisplayed: 0.1µF  [0402M]  (hidden comment: UMK105B7104MV-FR)
C44  VDC_V: 50V  ValueDisplayed: 0.1µF  [0402M]  (hidden comment: UMK105B7104MV-FR)
C45  VDC_V: 25V  ValueDisplayed: 10uF  [6032-28]  (hidden comment: TPSC106M025R0500)
C46  Cap_F: 4.7µF  VDC_V: 50V  [FP-CGA4J1X7R1H475K125AC_0805-IPC_A]  (hidden comment: CGA4J1X7R1H475K125AC)
C47  Cap_F: 4.7µF  VDC_V: 50V  [FP-CGA4J1X7R1H475K125AC_0805-IPC_A]  (hidden comment: CGA4J1X7R1H475K125AC)
C48  VDC_V: 20V  ValueDisplayed: 560uF  [FP-20SEF560M_RADIAL-MFG]  (hidden comment: 20SEF560M)
C49  VDC_V: 20V  ValueDisplayed: 560uF  [FP-20SEF560M_RADIAL-MFG]  (hidden comment: 20SEF560M)
C50  VDC_V: 25V  ValueDisplayed: 22µF  [1210_270M]  (hidden comment: CL32B226KAJNFNE)
C51  VDC_V: 25V  ValueDisplayed: 22µF  [1210_270M]  (hidden comment: CL32B226KAJNFNE)
C52  Cap_F: 1µF  VDC_V: 16V  [0805_HV]  (hidden comment: C0805C105K4RACAUTO)
C53  VDC_V: 50V  ValueDisplayed: 0.1µF  [0402M]  (hidden comment: UMK105B7104MV-FR)
C54  VDC_V: 50V  ValueDisplayed: 0.1µF  [0402M]  (hidden comment: UMK105B7104MV-FR)
C55  VDC_V: 50V  ValueDisplayed: 0.1µF  [0402M]  (hidden comment: UMK105B7104MV-FR)
C56  VDC_V: 20V  ValueDisplayed: 560uF  [FP-20SEF560M_RADIAL-MFG]  (hidden comment: 20SEF560M)
C57  VDC_V: 20V  ValueDisplayed: 560uF  [FP-20SEF560M_RADIAL-MFG]  (hidden comment: 20SEF560M)
C58  VDC_V: 25V  ValueDisplayed: 22µF  [1210_270M]  (hidden comment: CL32B226KAJNFNE)
C59  VDC_V: 25V  ValueDisplayed: 22µF  [1210_270M]  (hidden comment: CL32B226KAJNFNE)
C60  Cap_F: 1µF  VDC_V: 16V  [0805_HV]  (hidden comment: C0805C105K4RACAUTO)
C61  VDC_V: 50V  ValueDisplayed: 0.1µF  [0402M]  (hidden comment: UMK105B7104MV-FR)
C62  VDC_V: 50V  ValueDisplayed: 0.1µF  [0402M]  (hidden comment: UMK105B7104MV-FR)
C63  VDC_V: 50V  ValueDisplayed: 0.1µF  [0402M]  (hidden comment: UMK105B7104MV-FR)
C64  VDC_V: 25V  ValueDisplayed: 10uF  [6032-28]  (hidden comment: TPSC106M025R0500)
C65  Cap_F: 4.7µF  VDC_V: 50V  [FP-CGA4J1X7R1H475K125AC_0805-IPC_A]  (hidden comment: CGA4J1X7R1H475K125AC)
C66  VDC_V: 20V  ValueDisplayed: 560uF  [FP-20SEF560M_RADIAL-MFG]  (hidden comment: 20SEF560M)
C67  VDC_V: 20V  ValueDisplayed: 560uF  [FP-20SEF560M_RADIAL-MFG]  (hidden comment: 20SEF560M)
C68  VDC_V: 20V  ValueDisplayed: 560uF  [FP-20SEF560M_RADIAL-MFG]  (hidden comment: 20SEF560M)
C69  VDC_V: 20V  ValueDisplayed: 560uF  [FP-20SEF560M_RADIAL-MFG]  (hidden comment: 20SEF560M)
C70  VDC_V: 25V  ValueDisplayed: 22µF  [1210_270M]  (hidden comment: CL32B226KAJNFNE)
C71  VDC_V: 25V  ValueDisplayed: 22µF  [1210_270M]  (hidden comment: CL32B226KAJNFNE)
C72  Cap_F: 1µF  VDC_V: 16V  [0805_HV]  (hidden comment: C0805C105K4RACAUTO)
C73  VDC_V: 50V  ValueDisplayed: 0.1µF  [0402M]  (hidden comment: UMK105B7104MV-FR)
C74  VDC_V: 50V  ValueDisplayed: 0.1µF  [0402M]  (hidden comment: UMK105B7104MV-FR)
C75  VDC_V: 50V  ValueDisplayed: 0.1µF  [0402M]  (hidden comment: UMK105B7104MV-FR)
C76  Cap_F: 4.7µF  VDC_V: 50V  [FP-CGA4J1X7R1H475K125AC_0805-IPC_A]  (hidden comment: CGA4J1X7R1H475K125AC)
C77  VDC_V: 25V  ValueDisplayed: 22µF  [1210_270M]  (hidden comment: CL32B226KAJNFNE)
C78  VDC_V: 25V  ValueDisplayed: 22µF  [1210_270M]  (hidden comment: CL32B226KAJNFNE)
C79  Cap_F: 1µF  VDC_V: 16V  [0805_HV]  (hidden comment: C0805C105K4RACAUTO)
C80  VDC_V: 50V  ValueDisplayed: 0.1µF  [0402M]  (hidden comment: UMK105B7104MV-FR)
C81  VDC_V: 50V  ValueDisplayed: 0.1µF  [0402M]  (hidden comment: UMK105B7104MV-FR)
C82  VDC_V: 50V  ValueDisplayed: 0.1µF  [0402M]  (hidden comment: UMK105B7104MV-FR)
J26  JMP-36-30X40SMT  [JMP-36-30X40SMT]  (value not drawn)
J27  571-0500  [571-0500]  (value not drawn)
J28  TSW-102-07-G-D  [TSW-102-07-G-D]  (value not drawn)
J29  JMP-36-30X40SMT  [JMP-36-30X40SMT]  (value not drawn)
J30  691137710002  [FP-691137710002_HDR2-MFG]  (value not drawn)
J31  571-0100  [571-0100]  (value not drawn)
J32  JMP-36-30X40SMT  [JMP-36-30X40SMT]  (value not drawn)
R26  ValueDisplayed: 1.00  [0805_HV]  (hidden comment: ERJ-6BQF1R0V)
R27  ValueDisplayed: 1.00  [0805_HV]  (hidden comment: ERJ-6BQF1R0V)
R28  ValueDisplayed: 1.00  [0805_HV]  (hidden comment: ERJ-6BQF1R0V)

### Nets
GND: C27.1 C28.1(CATHODE) C29.1(CATHODE) C30.1(CATHODE) C31.1(CATHODE) C32.2 C33.2 C34.2 C35.2 C36.2 C37.2 C38.1 C39.2 C40.2 C41.2 C42.2 C43.2 C44.2 C46.1 C47.1 C48.1(CATHODE) C49.1(CATHODE) C50.2 C51.2 C52.2 C53.2 C54.2 C55.2 C56.1(CATHODE) C57.1(CATHODE) C58.2 C59.2 C60.2 C61.2 C62.2 C63.2 C65.1 C66.1(CATHODE) C67.1(CATHODE) C68.1(CATHODE) C69.1(CATHODE) C70.2 C71.2 C72.2 C73.2 C74.2 C75.2 C76.1 C77.2 C78.2 C79.2 C80.2 C81.2 C82.2 J26.1 J28.2 J28.4 J29.1 J30.1 J31.1 J31.2 J32.1 R26.1 R27.1 R28.1
VIN: C26.1(+) C27.2 C28.2(ANODE) C29.2(ANODE) C30.2(ANODE) C31.2(ANODE) C32.1 C33.1 C34.1 C35.1 C36.1 C37.1 C38.2 C39.1 C40.1 C41.1 C42.1 C43.1 C44.1 C45.1(+) C46.2 C47.2 C48.2(ANODE) C49.2(ANODE) C50.1 C51.1 C52.1 C53.1 C54.1 C55.1 C56.2(ANODE) C57.2(ANODE) C58.1 C59.1 C60.1 C61.1 C62.1 C63.1 C64.1(+) C65.2 C66.2(ANODE) C67.2(ANODE) C68.2(ANODE) C69.2(ANODE) C70.1 C71.1 C72.1 C73.1 C74.1 C75.1 C76.2 C77.1 C78.1 C79.1 C80.1 C81.1 C82.1 J27.1 J27.2 J28.1 J28.3 J30.2
NetC26_2: C26.2(-) J26.2 R26.2
NetC45_2: C45.2(-) J29.2 R27.2
NetC64_2: C64.2(-) J32.2 R28.2

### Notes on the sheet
- Rev
- N/A
- ECN #
- Approved Date
- Approved by
- Revision History
- Notes
- Current Sense
- Place Before Current Sense
- Place After Current Sense
- (near J27) 6 Vdc max
- (near J27) Banana Connector: 10A Max
- Screw Terminal: 16A Max
- (near J31) Banana Connector: 10A Max

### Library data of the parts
C26 C45 C64 = CMP-0011645-1: as C6 on sheet TIDA-050061_LDO
C27 C38 C46 C47 C65 C76 = CMP-0090082-1: Cap Ceramic 4.7uF 50V X7R 10% Pad SMD 0805 +125°C Automotive T/R; Manufacturer: TDK Corporation; SizeZ_mm: 1.45mm; Tolerance_%: 0.1%; AEC Qualified: Yes; TempCo: 15%; AEC Grade: Grade 1; Value: 4.7µF
C28-C31 C48 C49 C56 C57 C66-C69 = CMP-0093206-1: as C1 on sheet TIDA-050061_LDO
C32 C33 C39 C40 C50 C51 C58 C59 C70 C71 C77 C78 = CMP-0080066-1: CAP, CERM, 22 µF, 25 V,+/- 10%, X7R, 1210; Manufacturer: Samsung Electro-Mechanics; TaMin_C: -55°C; Polarized: N; SizeAreaWB_mm2: 14.7; U/M: EA; Value: 22uF; TaMax_C: 125°C; SizeZ_mm: 2.7; SizeX_mm: 3.2; SizeY_mm: 2.5; Cap_Case: 1210; SizeArea_mm2: 8; AEC Category: Q200
C34 C41 C52 C60 C72 C79 = CMP-0079630-1: CAP, CERM, 1 µF, 16 V,+/- 10%, X7R, AEC-Q200 Grade 1, 0805; Manufacturer: Kemet; TaMin_C: -55°C; Polarized: N; SizeAreaWB_mm2: 6.75; U/M: EA; Value: 1uF; TaMax_C: 125°C; SizeZ_mm: 1.45; SizeX_mm: 2; SizeY_mm: 1.25; Cap_Case: 0805; SizeArea_mm2: 2.5; AEC Qualified: Y; AEC Grade: 1; AEC Category: Q200
C35-C37 C42-C44 C53-C55 C61-C63 C73-C75 C80-C82 = CMP-0860570-1: CAP, CERM, 0.1 µF, 50 V,+/- 20%, X7R, 0402; Manufacturer: Taiyo Yuden; SizeAreaWB_mm2: 3; SizeZ_mm: 0.6; TaMax_C: 125°C; SizeY_mm: 0.5; TaMin_C: -55°C; Cap_Case: 0402; Cap_F: 100nF; AEC Category: Q200; U/M: EA; SizeX_mm: 1; Value: 0.1uF; Polarized: N
J26 J29 J32 = CMP-0003883-1: Jumper, SMT; Manufacturer: Any
J27 = CMP-0055393-3: as J2 on sheet TIDA-050061_LDO
J28 = CMP-0075404-1: as J6 on sheet TIDA-050061_LDO
J30 = CMP-0087503-1: as J11 on sheet TIDA-050061_LDO
J31 = CMP-0055389-3: as J9 on sheet TIDA-050061_LDO
R26-R28 = CMP-0074786-1: as R3 on sheet TIDA-050061_LDO

## Sheet TIDA-050061_Hardware.SchDoc
size 431 x 279 mm; Date: Not shown in title block; ApprovedBy: Not shown in title block; CheckedBy: Not shown in title block; Author: Not shown in title block; CompanyName: Not shown in title block; Engineer: Not shown in title block; Organization: Not shown in title block; Address1: Not shown in title block; Address2: Not shown in title block; Address3: Not shown in title block; Address4: Not shown in title block; DocumentNumber: 4; Revision: Use project parameter SCH_Rev; SheetNumber: 4; SheetTotal: 4; PageSetup: Record=PageOptions¦CenterHorizontal=True¦CenterVertical=True¦PrintScale=1.00¦XCorrection=1.00¦YCorrection=1.00¦PrintKind=0¦BorderSize=5000000¦LeftOffset=0¦BottomOffset=0¦Orientation=2¦PaperLength=1000¦PaperWidth=1000¦Scale=100¦PaperSource=15¦PrintQuality=600¦MediaType=1¦DitherType=10¦PaperKind=Letter¦PrintScaleMode=1
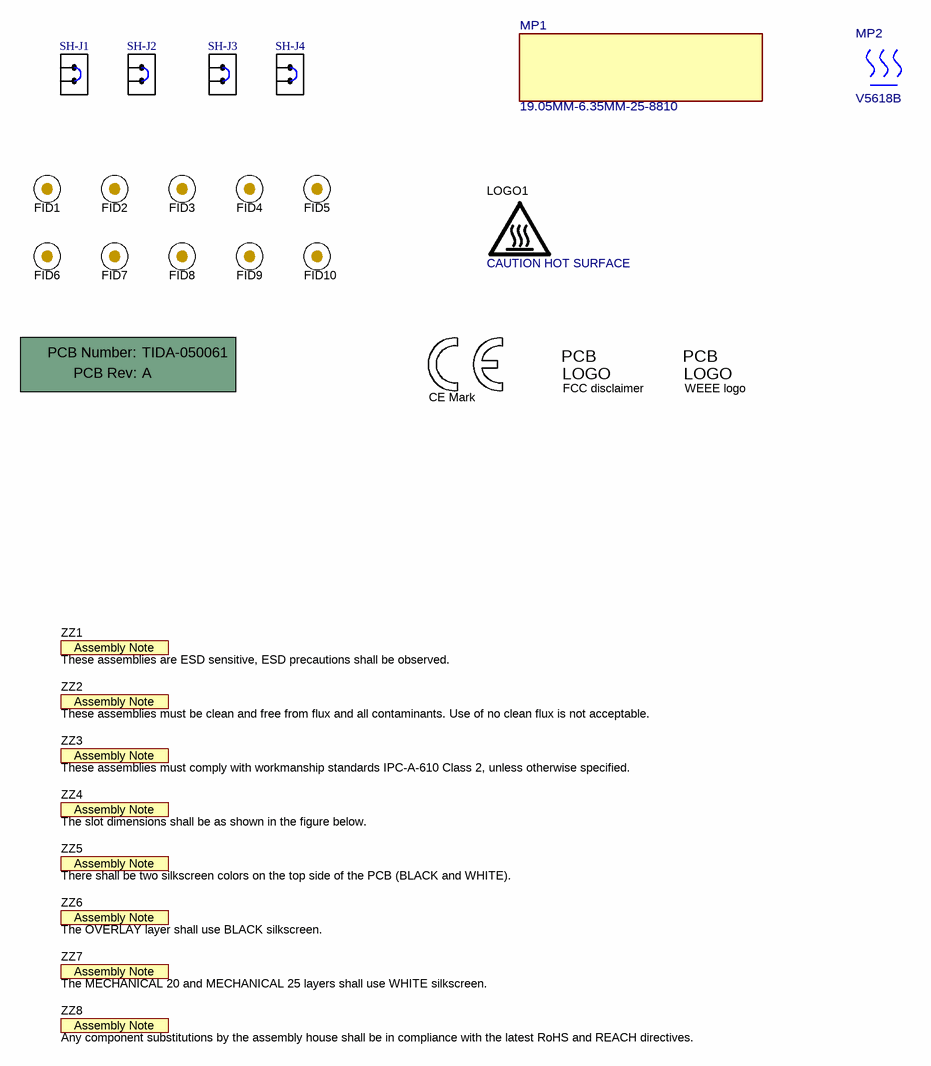
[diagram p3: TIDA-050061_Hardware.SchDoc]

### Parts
!PCB1  Printed Circuit Board  (value not drawn)  (mechanical)
FID1  Fiducial  [Fiducial10-20]  (value not drawn)
FID2  Fiducial  [Fiducial10-20]  (value not drawn)
FID3  Fiducial  [Fiducial10-20]  (value not drawn)
FID4  Fiducial  [Fiducial10-20]  (value not drawn)
FID5  Fiducial  [Fiducial10-20]  (value not drawn)
FID6  Fiducial  [Fiducial10-20]  (value not drawn)
FID7  Fiducial  [Fiducial10-20]  (value not drawn)
FID8  Fiducial  [Fiducial10-20]  (value not drawn)
FID9  Fiducial  [Fiducial10-20]  (value not drawn)
FID10  Fiducial  [Fiducial10-20]  (value not drawn)
LOGO1  CAUTION HOT SURFACE  [IEC_HotSurface_Small]  (no BOM)
Logo2  CE Mark  [CE_Mark_5mm]  (no BOM)
Logo4  FCC disclaimer  [FCC_disclaimer]  (no BOM)
Logo5  WEEE logo  [WEEE_Minimum]  (no BOM)
MP1  19.05MM-6.35MM-25-8810  [FP-19.05MM-6.35MM-25-8810_THERMAL_PAD-MFG]
MP2  V5618B  [FP-V5618B_HEATSINK-MFG]
SH-J1  SNT-100-BK-G  [SNT-100-BK-G]  (value not drawn)
SH-J2  SNT-100-BK-G  [SNT-100-BK-G]  (value not drawn)
SH-J3  SNT-100-BK-G  [SNT-100-BK-G]  (value not drawn)
SH-J4  SNT-100-BK-G  [SNT-100-BK-G]  (value not drawn)
ZZ1  These assemblies are ESD sensitive, ESD precautions shall be observed.  [AssemblyNote]  (no BOM)
ZZ2  These assemblies must be clean and free from flux and all contaminants. Use of no clean flux is not acceptable.  [AssemblyNote]  (no BOM)
ZZ3  These assemblies must comply with workmanship standards IPC-A-610 Class 2, unless otherwise specified.  [AssemblyNote]  (no BOM)
ZZ4  The slot dimensions shall be as shown in the figure below.  [AssemblyNote]  (no BOM)
ZZ5  There shall be two silkscreen colors on the top side of the PCB (BLACK and WHITE).  [AssemblyNote]  (no BOM)
ZZ6  The OVERLAY layer shall use BLACK silkscreen.  [AssemblyNote]  (no BOM)
ZZ7  The MECHANICAL 20 and MECHANICAL 25 layers shall use WHITE silkscreen.  [AssemblyNote]  (no BOM)
ZZ8  Any component substitutions by the assembly house shall be in compliance with the latest RoHS and REACH directives.  [AssemblyNote]  (no BOM)

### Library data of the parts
!PCB1 = CMP-0003618-2: Manufacturer: Any; PartNumber: TIDA-050061
FID1-FID10 = CMP-0077181-1: Fiducial mark.  There is nothing to buy or mount.
LOGO1 = CMP-0074837-1: IEC 61010-1 Hot Surface Warning; SymbolCreator: a0412235
Logo2 = CMP-0074844-1: SymbolCreator: a0412235
Logo4 = CMP-0074847-1: FCC_disclaimer; Library Reference: Logo
Logo5 = CMP-0074769-1
MP1 = CMP-0095762-1: Thermal Pad White 19.05mm x 6.35mm Rectangular Adhesive - Both Sides; Manufacturer: 3M; AEC Qualified: No
MP2 = CMP-0096629-1: Heatsink, 46 K/W, 19x6.3x4.8 mm, black anodized; Manufacturer: Assmann WSW Components; AEC Qualified: No; SizeZ_mm: 5.2mm; Natural Thermal Resistance: 46°C/W
SH-J1-SH-J4 = CMP-0003623-3: Shunt, 100mil, Gold plated, Black; Manufacturer: Samtec; Alternate Manufacturer: 3M; Alternate PartNumber: 969102-0000-DA; Value: 1x2; Note: You can "mate" this to a header by matching the designator.  i.e. use SH-J3 for header J3
ZZ1 = CMP-0077236-1
ZZ2 = CMP-0077237-1
ZZ3 = CMP-0077238-1
ZZ4-ZZ8 = CMP-0077238-1: The tab route width shall be between 80 mils and 120 mils; CompType: FabricationNote

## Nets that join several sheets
GND: TIDA-050061_LDO (56 pins), TIDA-050061_Load (26 pins), TIDA-050061_Input_Cap (65 pins)
VIN: TIDA-050061_LDO (18 pins), TIDA-050061_Input_Cap (62 pins)
VOUT: TIDA-050061_LDO (10 pins), TIDA-050061_Load (7 pins)

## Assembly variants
001: not fitted C1 C2 C5 C6 C10 C14 C18 C19 C20 C24 C25 C26 C28 C29 C38 C39 C40 C41 C42 C43 C44 C45 C46 C48 C49 C50 C51 C52 C53 C54 C55 C64 C66 C67 C76 C77 C78 C79 C80 C81 C82 FID1 FID2 FID3 FID4 FID5 FID6 FID7 FID8 FID9 FID10 J3 J6 J8 J10 J16 J24 J26 J28 J29 J32 R3 R6 R11 R12 R13 R14 R15 R16 R17 R18 R21 R22 R23 R24 R26 R27 R28 SH-J1 SH-J2 SH-J3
